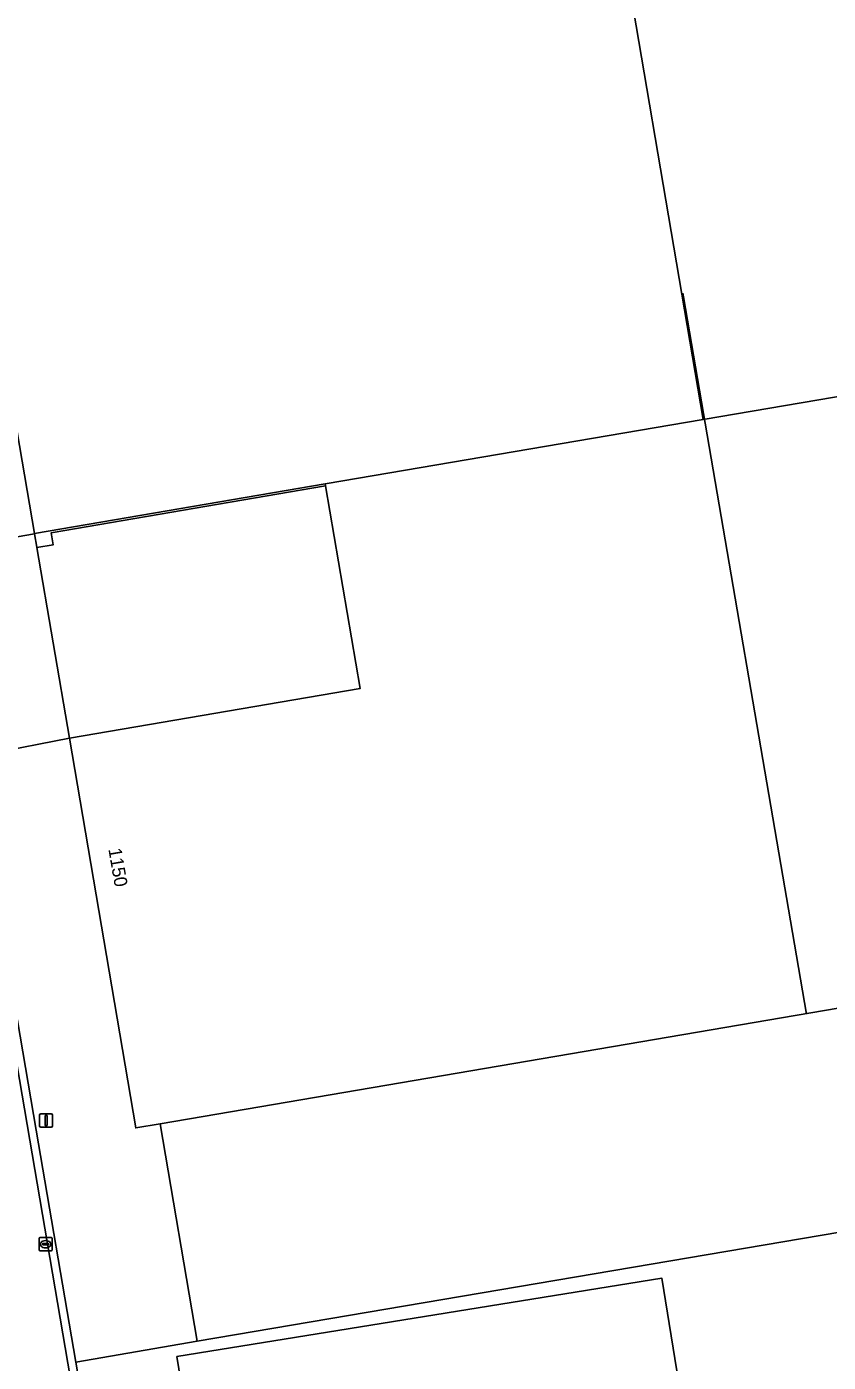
# Model space of a CAD drawing. Extents: x 154324 to 155744, y 382937 to 384188.
# Drawn here: x 154882.3 to 154943.2, y 383668.1 to 383769.7 of the extents above; entities that cross this region are included whole.
import ezdxf

# ---------------------------------------------------------------- set-up
doc = ezdxf.new("R2010")
doc.units = 0
for name, color, linetype in [('IMGEO_Erf', 7, 'Continuous'), ('IMGEO_Grasland_agrarisch', 7, 'Continuous'), ('IMGEO_Hek', 7, 'Continuous'), ('IMGEO_Kolk', 7, 'Continuous'), ('IMGEO_Lichtmast', 7, 'Continuous'), ('IMGEO_Muur', 7, 'Continuous'), ('IMGEO_Pand', 7, 'Continuous'), ('IMGEO_Pand_nummerreeks', 7, 'Continuous'), ('IMGEO_Pand_vergunning_verleend', 7, 'Continuous'), ('IMGEO_Rijbaan_lokaal_gesloten', 7, 'Continuous'), ('IMGEO_Rijbaan_lokaal_open', 7, 'Continuous'), ('IMGEO_Voetpad_open', 7, 'Continuous')]:
    doc.layers.add(name, color=color, linetype=linetype)

msp = doc.modelspace()

# ---------------------------------------------------------------- linework, layer by layer
at = {"layer": 'IMGEO_Erf'}
msp.add_lwpolyline([(154925.99, 383785.24), (154933.72, 383739.79), (154944.89, 383741.69), (154944.88, 383741.74), (155001.21, 383751.34), (155008.93, 383706.03), (154952.61, 383696.43), (154952.6, 383696.48), (154892.43, 383686.21), (154895.24, 383669.68), (154944.1, 383677.97), (154949.33, 383647.91), (154982.71, 383457.88)], dxfattribs=at)
msp.add_lwpolyline([(154905.01, 383734.73), (154884.14, 383731.16), (154884.3, 383730.25), (154883.05, 383730.04), (154885.53, 383715.54), (154907.63, 383719.32)], close=True, dxfattribs=at)
at = {"layer": 'IMGEO_Grasland_agrarisch'}
msp.add_lwpolyline([(154982.71, 383457.88), (154949.33, 383647.91), (154944.1, 383677.97), (154895.24, 383669.68), (154886.01, 383668.1), (154936.69, 383370.6)], dxfattribs=at)
at = {"layer": 'IMGEO_Hek'}
msp.add_lwpolyline([(154932.18, 383749.38), (154932.22, 383749.12), (154941.57, 383694.55)], dxfattribs=at)
at = {"layer": 'IMGEO_Kolk'}
for p, q in [((154883.22, 383676.64), (154883.22, 383677.49)), ((154883.29, 383677.56), (154884.15, 383677.56)), ((154883.48, 383677.06), (154883.48, 383677.07)), ((154883.52, 383677.11), (154883.92, 383677.11)), ((154883.92, 383677.02), (154883.52, 383677.02)), ((154883.71, 383677.34), (154883.73, 383677.34)), ((154883.96, 383677.07), (154883.96, 383677.06)), ((154884.22, 383677.49), (154884.22, 383676.64)), ((154884.15, 383676.56), (154883.29, 383676.56)), ((154883.73, 383676.78), (154883.7, 383676.78))]:
    msp.add_line(p, q, dxfattribs=at)
for points in [[(154883.22, 383676.64), (154883.22, 383677.49)], [(154883.29, 383677.56), (154884.15, 383677.56)], [(154884.22, 383677.49), (154884.22, 383676.64)], [(154884.15, 383676.56), (154883.29, 383676.56)]]:
    msp.add_lwpolyline(points, dxfattribs=at)
for centre, radius, start, end in [((154883.3, 383677.49), 0.0765, 91.552, 178.448), ((154883.3, 383677.49), 0.0765, 91.552, 178.448), ((154883.52, 383677.07), 0.0403, 85.8775, 175.7526), ((154883.51, 383677.06), 0.0366, 178.938, 274.7102), ((154883.92, 383677.07), 0.0386, 1.7309, 96.639), ((154883.92, 383677.06), 0.043, 264.8664, 352.4533), ((154884.14, 383677.49), 0.0765, 1.552, 88.448), ((154884.14, 383677.49), 0.0765, 1.552, 88.448), ((154883.3, 383676.64), 0.0765, 181.552, 268.448), ((154883.3, 383676.64), 0.0765, 181.552, 268.448), ((154884.14, 383676.64), 0.0765, 271.552, 358.448), ((154884.14, 383676.64), 0.0765, 271.552, 358.448)]:
    msp.add_arc(centre, radius, start, end, dxfattribs=at)
for centre, major_axis, ratio, start_param, end_param in [((154883.71, 383677.06), (-0.387, 0.002), 0.722429, 4.712389, 7.853982), ((154883.73, 383677.06), (-0.39, 0.002), 0.717154, 1.570796, 4.712389)]:
    msp.add_ellipse(centre, major_axis=major_axis, ratio=ratio, start_param=start_param, end_param=end_param, dxfattribs=at)
at = {"layer": 'IMGEO_Lichtmast'}
for p, q in [((154883.36, 383686.97), (154884.15, 383686.97)), ((154884.15, 383686.97), (154883.36, 383686.97)), ((154883.26, 383686.07), (154883.26, 383686.87)), ((154883.26, 383686.87), (154883.26, 383686.07)), ((154884.15, 383685.97), (154883.36, 383685.97)), ((154883.36, 383685.97), (154884.15, 383685.97)), ((154884.25, 383686.87), (154884.25, 383686.07)), ((154884.25, 383686.07), (154884.25, 383686.87))]:
    msp.add_line(p, q, dxfattribs=at)
msp.add_lwpolyline([(154883.68, 383686.85), (154883.83, 383686.85), (154883.83, 383686.1), (154883.68, 383686.1), (154883.68, 383686.85)], dxfattribs=at)
for centre, start, end in [((154883.36, 383686.87), 90, 180), ((154883.36, 383686.87), 90, 180), ((154884.15, 383686.87), 0, 90), ((154884.15, 383686.87), 360, 90), ((154883.36, 383686.07), 180, 270), ((154883.36, 383686.07), 180, 270), ((154884.15, 383686.07), 270, 0), ((154884.15, 383686.07), 270, 0)]:
    msp.add_arc(centre, 0.1, start, end, dxfattribs=at)
at = {"layer": 'IMGEO_Muur'}
msp.add_lwpolyline([(154884.14, 383731.16), (154905.01, 383734.73), (154904.98, 383734.88), (154882.87, 383731.11), (154882.88, 383731.08), (154883.05, 383730.08), (154883.05, 383730.04), (154884.3, 383730.25)], close=True, dxfattribs=at)
at = {"layer": 'IMGEO_Pand'}
for points in [[(154925.99, 383785.24), (154875.1, 383776.59), (154875.11, 383776.48), (154882.87, 383731.11), (154904.98, 383734.88), (154933.72, 383739.79)], [(154944.89, 383741.69), (154933.72, 383739.79), (154904.98, 383734.88), (154905.01, 383734.73), (154907.63, 383719.32), (154885.53, 383715.54), (154890.57, 383685.9), (154892.43, 383686.21), (154952.6, 383696.48)]]:
    msp.add_lwpolyline(points, close=True, dxfattribs=at)
at = {"layer": 'IMGEO_Pand_vergunning_verleend'}
msp.add_lwpolyline([(154893.69, 383668.53), (154930.56, 383674.49), (154935.25, 383645.51), (154898.38, 383639.55)], close=True, dxfattribs=at)
at = {"layer": 'IMGEO_Rijbaan_lokaal_gesloten'}
msp.add_lwpolyline([(154961.84, 383219.4), (154937.89, 383359.92), (154875.73, 383724.69)], dxfattribs=at)
at = {"layer": 'IMGEO_Rijbaan_lokaal_open'}
for points in [[(154886.01, 383668.1), (154883, 383685.74), (154876.35, 383724.76), (154875.86, 383727.69), (154875.5, 383729.82), (154873.58, 383740.95), (154869.8, 383763.15), (154867.75, 383775.23), (154861.32, 383812.98), (154859.63, 383822.86)], [(154859.21, 383821.78), (154860.59, 383813.67), (154872.99, 383740.87), (154875.26, 383727.61), (154875.73, 383724.69), (154937.89, 383359.92), (154938.49, 383360.02), (154937.7, 383364.67), (154936.71, 383370.48), (154936.7, 383370.54), (154936.69, 383370.6), (154886.01, 383668.1)]]:
    msp.add_lwpolyline(points, dxfattribs=at)
at = {"layer": 'IMGEO_Voetpad_open'}
for points in [[(154885.53, 383715.54), (154879.55, 383714.38), (154876.86, 383730.05), (154882.88, 383731.08), (154882.87, 383731.11), (154875.11, 383776.48), (154867.75, 383775.23), (154869.8, 383763.15), (154873.58, 383740.95), (154875.5, 383729.82), (154875.86, 383727.69), (154876.35, 383724.76), (154883, 383685.74), (154886.01, 383668.1), (154895.24, 383669.68), (154892.43, 383686.21), (154890.57, 383685.9)], [(154883.05, 383730.04), (154883.05, 383730.08), (154882.88, 383731.08), (154876.86, 383730.05), (154879.55, 383714.38), (154885.53, 383715.54)]]:
    msp.add_lwpolyline(points, close=True, dxfattribs=at)

# ---------------------------------------------------------------- texts
at = {"layer": 'IMGEO_Pand_nummerreeks'}
msp.add_text('1150', height=1, rotation=279.6541, dxfattribs=at).set_placement((154888.49, 383707.11))

doc.saveas('drawing.dxf')
